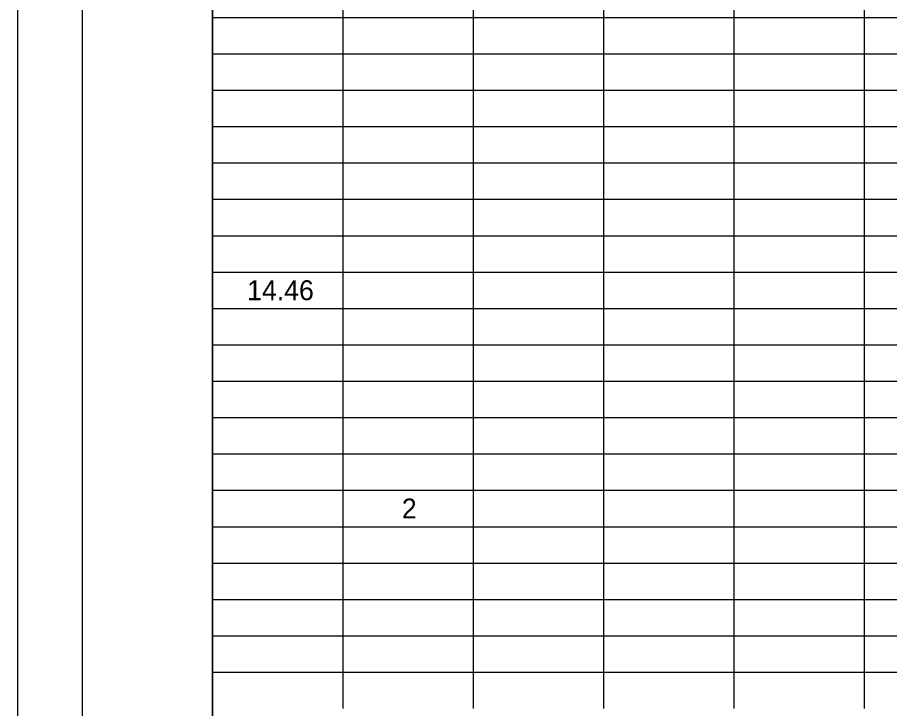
# Model space of a CAD drawing. Extents: x 0 to 34, y 0 to 22.
# Drawn here: x 0 to 6.71, y 11.42 to 16.74 of the extents above; entities that cross this region are included whole.
import ezdxf

# ---------------------------------------------------------------- set-up
doc = ezdxf.new("R2010")
doc.units = 0
for name, color, linetype in [('SH_Border', 7, 'Continuous'), ('SH_Cut_Line', 7, 'Continuous'), ('SH_Text', 7, 'Continuous')]:
    doc.layers.add(name, color=color, linetype=linetype)

msp = doc.modelspace()

# ---------------------------------------------------------------- linework, layer by layer
at = {"layer": 'SH_Border'}
for points in [[(0.5, 21.5), (1.5, 21.5), (1.5, 0.5), (0.5, 0.5)], [(1.5, 21.5), (33.5, 21.5), (33.5, 0.5), (1.5, 0.5)]]:
    msp.add_lwpolyline(points, close=True, dxfattribs=at)
at = {"layer": 'SH_Cut_Line'}
msp.add_lwpolyline([(0, 0), (34, 0), (34, 22), (0, 22)], close=True, dxfattribs=at)
at = {"layer": 'SH_Text'}
for p, q in [((1.5, 17.0199), (1.5, 16.7399)), ((2.5027, 17.0199), (2.5027, 16.7399)), ((3.5053, 17.0199), (3.5053, 16.7399)), ((4.508, 17.0199), (4.508, 16.7399)), ((5.5106, 17.0199), (5.5106, 16.7399)), ((6.5133, 17.0199), (6.5133, 16.7399)), ((1.5, 16.7399), (6.5133, 16.7399)), ((1.5, 16.7399), (1.5, 16.1799)), ((2.5027, 16.7399), (2.5027, 16.1799)), ((3.5053, 16.7399), (3.5053, 16.1799)), ((4.508, 16.7399), (4.508, 16.1799)), ((5.5106, 16.7399), (5.5106, 16.1799)), ((6.5133, 16.7399), (7.516, 16.7399)), ((6.5133, 16.7399), (6.5133, 16.1799)), ((1.5, 16.4599), (6.5133, 16.4599)), ((6.5133, 16.4599), (7.516, 16.4599)), ((1.5, 16.1799), (6.5133, 16.1799)), ((1.5, 16.1799), (1.5, 15.8999)), ((2.5027, 16.1799), (2.5027, 15.8999)), ((3.5053, 16.1799), (3.5053, 15.8999)), ((4.508, 16.1799), (4.508, 15.8999)), ((5.5106, 16.1799), (5.5106, 15.8999)), ((6.5133, 16.1799), (7.516, 16.1799)), ((6.5133, 16.1799), (6.5133, 15.8999)), ((1.5, 15.8999), (6.5133, 15.8999)), ((1.5, 15.8999), (1.5, 15.6198)), ((2.5027, 15.8999), (2.5027, 15.6198)), ((3.5053, 15.8999), (3.5053, 15.6198)), ((4.508, 15.8999), (4.508, 15.6198)), ((5.5106, 15.8999), (5.5106, 15.6198)), ((6.5133, 15.8999), (7.516, 15.8999)), ((6.5133, 15.8999), (6.5133, 15.6198)), ((1.5, 15.6198), (6.5133, 15.6198)), ((1.5, 15.6198), (1.5, 15.3398)), ((2.5027, 15.6198), (2.5027, 15.3398)), ((3.5053, 15.6198), (3.5053, 15.3398)), ((4.508, 15.6198), (4.508, 15.3398)), ((5.5106, 15.6198), (5.5106, 15.3398)), ((6.5133, 15.6198), (7.516, 15.6198)), ((6.5133, 15.6198), (6.5133, 15.3398)), ((1.5, 15.3398), (6.5133, 15.3398)), ((1.5, 15.3398), (1.5, 14.7798)), ((2.5027, 15.3398), (2.5027, 14.7798)), ((3.5053, 15.3398), (3.5053, 14.7798)), ((4.508, 15.3398), (4.508, 14.7798)), ((5.5106, 15.3398), (5.5106, 14.7798)), ((6.5133, 15.3398), (7.516, 15.3398)), ((6.5133, 15.3398), (6.5133, 14.7798)), ((1.5, 15.0598), (6.5133, 15.0598)), ((6.5133, 15.0598), (7.516, 15.0598)), ((1.5, 14.7798), (6.5133, 14.7798)), ((1.5, 14.7798), (1.5, 14.4998)), ((2.5027, 14.7798), (2.5027, 14.4998)), ((3.5053, 14.7798), (3.5053, 14.4998)), ((4.508, 14.7798), (4.508, 14.4998)), ((5.5106, 14.7798), (5.5106, 14.4998)), ((6.5133, 14.7798), (7.516, 14.7798)), ((6.5133, 14.7798), (6.5133, 14.4998)), ((1.5, 14.4998), (6.5133, 14.4998)), ((1.5, 14.4998), (1.5, 14.2198)), ((2.5027, 14.4998), (2.5027, 14.2198)), ((3.5053, 14.4998), (3.5053, 14.2198)), ((4.508, 14.4998), (4.508, 14.2198)), ((5.5106, 14.4998), (5.5106, 14.2198)), ((6.5133, 14.4998), (7.516, 14.4998)), ((6.5133, 14.4998), (6.5133, 14.2198)), ((1.5, 14.2198), (6.5133, 14.2198)), ((1.5, 14.2198), (1.5, 13.9398)), ((2.5027, 14.2198), (2.5027, 13.9398)), ((3.5053, 14.2198), (3.5053, 13.9398)), ((4.508, 14.2198), (4.508, 13.9398)), ((5.5106, 14.2198), (5.5106, 13.9398)), ((6.5133, 14.2198), (7.516, 14.2198)), ((6.5133, 14.2198), (6.5133, 13.9398)), ((1.5, 13.9398), (6.5133, 13.9398)), ((1.5, 13.9398), (1.5, 11.6997)), ((2.5027, 13.9398), (2.5027, 11.6997)), ((3.5053, 13.9398), (3.5053, 11.6997)), ((4.508, 13.9398), (4.508, 11.6997)), ((5.5106, 13.9398), (5.5106, 11.6997)), ((6.5133, 13.9398), (7.516, 13.9398)), ((6.5133, 13.9398), (6.5133, 11.6997)), ((1.5, 13.6598), (6.5133, 13.6598)), ((6.5133, 13.6598), (7.516, 13.6598)), ((1.5, 13.3798), (6.5133, 13.3798)), ((6.5133, 13.3798), (7.516, 13.3798)), ((1.5, 13.0998), (6.5133, 13.0998)), ((6.5133, 13.0998), (7.516, 13.0998)), ((1.5, 12.8198), (6.5133, 12.8198)), ((6.5133, 12.8198), (7.516, 12.8198)), ((1.5, 12.5398), (6.5133, 12.5398)), ((6.5133, 12.5398), (7.516, 12.5398)), ((1.5, 12.2598), (6.5133, 12.2598)), ((6.5133, 12.2598), (7.516, 12.2598)), ((1.5, 11.9798), (6.5133, 11.9798)), ((6.5133, 11.9798), (7.516, 11.9798)), ((1.5, 11.6997), (6.5133, 11.6997)), ((1.5, 11.6997), (1.5, 11.4197)), ((2.5027, 11.6997), (2.5027, 11.4197)), ((3.5053, 11.6997), (3.5053, 11.4197)), ((4.508, 11.6997), (4.508, 11.4197)), ((5.5106, 11.6997), (5.5106, 11.4197)), ((6.5133, 11.6997), (7.516, 11.6997)), ((6.5133, 11.6997), (6.5133, 11.4197))]:
    msp.add_line(p, q, dxfattribs=at)

# ---------------------------------------------------------------- texts
for s, height, p in [('14.46', 0.15334, (1.7666, 14.5632)), ('2', 0.1533, (2.9567, 12.8831))]:
    msp.add_text(s, height=height, dxfattribs=at).set_placement(p)

doc.saveas('drawing.dxf')
